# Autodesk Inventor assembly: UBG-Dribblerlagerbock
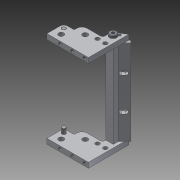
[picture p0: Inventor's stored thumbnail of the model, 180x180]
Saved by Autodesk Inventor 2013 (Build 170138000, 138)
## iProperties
Created: 2012-07
Part Number: UBG-Dribblerlagerbock
Document SubType Name: Assembly
Designer: rYan
Mass: 33.2804 g
Surface Area: 98.1353 cm^2
Volume: 10.865 cm^3
Density: 3.06308 g/cm^3
Author: rYan
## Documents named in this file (6)
- D:\SVN\2013\Inventor\Dribbling Device\UBG-Dribblerlagerbock.iam
- D:\SVN\2013\Inventor\Dribbling Device\Chipperstuetze.ipt
- D:\SVN\2013\Inventor\Dribbling Device\Dribblerfaenger.ipt
- D:\SVN\2013\Inventor\Inhaltscenter\de-DE\DIN 7984\DIN 7984 - M3 x 8.ipt
- D:\SVN\2013\Inventor\Inhaltscenter\en-US\DIN ISO 8734(1)\ISO 8734 - 2 x 6 - ADIN EN.ipt
- D:\SVN\2013\Inventor\Inhaltscenter\en-US\ISO 2338(1)\ISO 2338 - 3 m6 x 8DIN EN.ipt
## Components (9 placed, 5 different names)
1. Chipperstütze:1 — Passend:1, Passend:16, Passend:18, Fluchtend:10, Passend:19, Passend:23
2. Chipperstütze:2 — Passend:2, Passend:14, Passend:17, Fluchtend:9, Passend:20, Passend:22
3. Dribblerfänger:1 — Passend:1, Passend:2, Passend:19, Passend:20, Passend:22, Passend:23
4. DIN 7984 M3 x 8:5 — Passend:14
5. DIN 7984 M3 x 8:6 — Passend:16
6. DIN EN ISO 8734 2 x 6 - A:1 — Passend:18, Fluchtend:10
7. DIN EN ISO 8734 2 x 6 - A:2 — Passend:17, Fluchtend:9
8. DIN EN ISO 2338 3 m6 x 8:1
9. DIN EN ISO 2338 3 m6 x 8:2
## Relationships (12: Mate 10, Flush 2)
- Passend:1 [Mate]: Chipperstütze:1 ↔ Dribblerfänger:1
- Passend:2 [Mate]: Chipperstütze:2 ↔ Dribblerfänger:1
- Passend:14 [Mate]: Chipperstütze:2 ↔ DIN 7984 M3 x 8:5
- Passend:16 [Mate]: Chipperstütze:1 ↔ DIN 7984 M3 x 8:6
- Passend:17 [Mate]: Chipperstütze:2 ↔ DIN EN ISO 8734 2 x 6 - A:2
- Fluchtend:9 [Flush]: Chipperstütze:2 ↔ DIN EN ISO 8734 2 x 6 - A:2
- Passend:18 [Mate]: Chipperstütze:1 ↔ DIN EN ISO 8734 2 x 6 - A:1
- Fluchtend:10 [Flush]: Chipperstütze:1 ↔ DIN EN ISO 8734 2 x 6 - A:1
- Passend:19 [Mate]: Chipperstütze:1 ↔ Dribblerfänger:1
- Passend:20 [Mate]: Chipperstütze:2 ↔ Dribblerfänger:1
- Passend:22 [Mate]: Chipperstütze:2 ↔ Dribblerfänger:1
- Passend:23 [Mate]: Chipperstütze:1 ↔ Dribblerfänger:1
